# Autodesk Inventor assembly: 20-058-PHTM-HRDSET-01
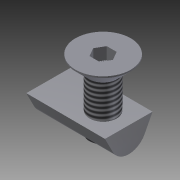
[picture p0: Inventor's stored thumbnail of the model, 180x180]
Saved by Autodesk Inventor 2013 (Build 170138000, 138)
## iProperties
Created: 2004-11
Part Number: 20-058-PHTM-HRDSET-01
Document SubType Name: Assembly
Designer: Autodesk, Inc.
Manufacturer: Standard
Standards Organization: Custom
Description: MISC HADWARE SET PHANTOM
Catalog Web Link: http://www.parker.com/ead/cm1.asp?cmid=809
Vendor: PARKER IPS
Mass: 20.6231 g
Surface Area: 19.5872 cm^2
Volume: 2.63049 cm^3
Density: 7.84 g/cm^3
CAGE: 1LJX3
Dept. ID: Product Design
Description #2: ---
Finish #1: ---
Finish #2: ---
Material ID: ---
Project Number: ---
Author: Autodesk, Inc.
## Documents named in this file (5)
- Z:\_DATEN\Test Station\Components\M178-1000-Phantom01.iam
- Z:\_DATEN\Test Station\Components\24-220-8.ipt
- Z:\_DATEN\Test Station\Components\20-058.ipt
- C:\Users\kelleyb.ADS\Desktop\Samples MIGRATED 2009 224 RTM_1\Standard Parts\Test Station Content\Fastners\2X-YYY-ZZ IPS Screws.ipt
- C:\Users\kelleyb.ADS\Desktop\Samples MIGRATED 2009 224 RTM_1\Standard Parts\Test Station Content\Fastners\20-XXX TSlot Nuts.ipt
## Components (2 placed, 2 different names)
1. 24-220-8:1
2. 20-058:1
